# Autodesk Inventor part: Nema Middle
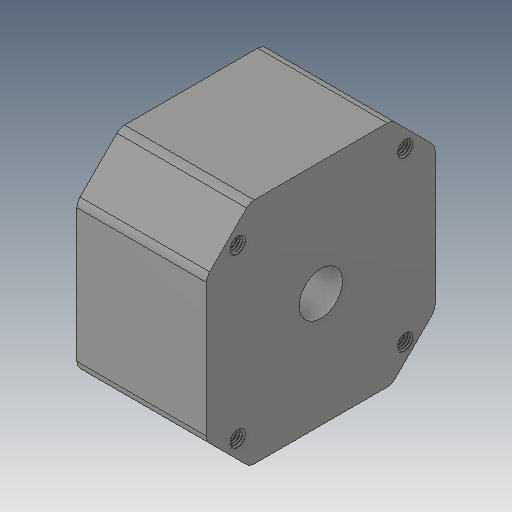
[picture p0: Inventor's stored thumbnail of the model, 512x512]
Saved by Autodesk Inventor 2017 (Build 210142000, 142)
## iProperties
Created: 2018-08
Part Number: Nema Middle
Material: Stainless Steel, Brushed
Document SubType Name: Modeling
Designer: JK
Density: 8 g/cm^3
Appearance: Stainless - Brushed
Author: JK
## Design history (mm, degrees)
feature "Body1"
body "Solid1"
